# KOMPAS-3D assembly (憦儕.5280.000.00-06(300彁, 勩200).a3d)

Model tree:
1. Плоскость XY
2. Плоскость ZX
3. Плоскость ZY
4. Ось X
5. Ось Y
6. Ось Z
7. Начало координат  (labels: Операция без истории:1; Операция без истории:2; Операция без истории:3; Операция без истории:4)

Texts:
  Линия-выноска #1
  Линия-выноска #2
  Линия-выноска #3
  Отклонения формы и база
  Марка координационной оси
  Марка/позиционное обозначение с линией-выноской
  Марка/позиционное обозначение на линии
  Марка/позиционное обозначение без линии-выноски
